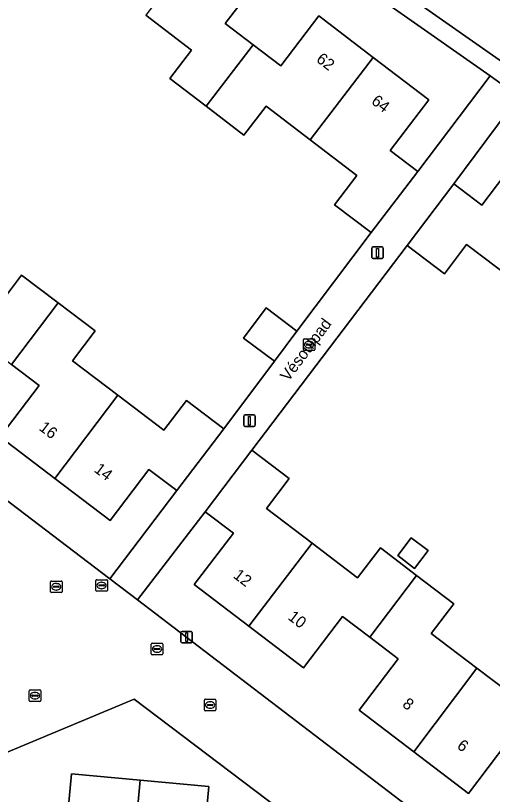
# Model space of a CAD drawing. Extents: x 158472 to 159562, y 388525 to 389606.
# Drawn here: x 158657.8 to 158699.2, y 389050.2 to 389117.7 of the extents above; entities that cross this region are included whole.
import ezdxf

# ---------------------------------------------------------------- set-up
doc = ezdxf.new("R2010")
doc.units = 0
for name, color, linetype in [('IMGEO_Brandkraan', 7, 'Continuous'), ('IMGEO_Erf', 7, 'Continuous'), ('IMGEO_Kolk', 7, 'Continuous'), ('IMGEO_Lichtmast', 7, 'Continuous'), ('IMGEO_Openbare_ruimte_label', 7, 'Continuous'), ('IMGEO_Pand', 7, 'Continuous'), ('IMGEO_Pand_nummerreeks', 7, 'Continuous'), ('IMGEO_Rijbaan_lokaal_open', 7, 'Continuous'), ('IMGEO_Rioolput', 7, 'Continuous')]:
    doc.layers.add(name, color=color, linetype=linetype)

msp = doc.modelspace()

# ---------------------------------------------------------------- linework, layer by layer
at = {"layer": 'IMGEO_Brandkraan'}
for p, q in [((158664.798, 389067.88), (158664.798, 389068.732)), ((158664.873, 389068.806), (158665.725, 389068.806)), ((158665.057, 389068.3), (158665.057, 389068.312)), ((158665.495, 389068.263), (158665.097, 389068.263)), ((158665.1, 389068.349), (158665.498, 389068.349)), ((158665.286, 389068.586), (158665.311, 389068.586)), ((158665.541, 389068.312), (158665.541, 389068.3)), ((158665.799, 389068.732), (158665.799, 389067.88)), ((158665.725, 389067.806), (158664.873, 389067.806)), ((158665.309, 389068.026), (158665.284, 389068.026))]:
    msp.add_line(p, q, dxfattribs=at)
for points in [[(158664.798, 389067.88), (158664.798, 389068.732)], [(158664.873, 389068.806), (158665.725, 389068.806)], [(158665.799, 389068.732), (158665.799, 389067.88)], [(158665.725, 389067.806), (158664.873, 389067.806)]]:
    msp.add_lwpolyline(points, dxfattribs=at)
for centre, radius, start, end in [((158664.875, 389068.73), 0.0765, 91.55205, 178.44795), ((158664.875, 389068.73), 0.0765, 91.55205, 178.44795), ((158665.097, 389068.309), 0.0403, 85.87752, 175.75265), ((158665.094, 389068.299), 0.0366, 178.93798, 274.71019), ((158665.498, 389068.306), 0.043, 264.86636, 352.45326), ((158665.502, 389068.311), 0.0386, 1.73085, 96.63898), ((158665.723, 389068.73), 0.0765, 1.55205, 88.44795), ((158665.723, 389068.73), 0.0765, 1.55205, 88.44795), ((158664.875, 389067.882), 0.0765, 181.55205, 268.44795), ((158664.875, 389067.882), 0.0765, 181.55205, 268.44795), ((158665.723, 389067.882), 0.0765, 271.55205, 358.44795), ((158665.723, 389067.882), 0.0765, 271.55205, 358.44795)]:
    msp.add_arc(centre, radius, start, end, dxfattribs=at)
for centre, major_axis, ratio, start_param, end_param in [((158665.285, 389068.306), (-0.387, 0.002), 0.722429, 4.712389, 7.853982), ((158665.31, 389068.306), (-0.39, 0.002), 0.717154, 1.570796, 4.712389)]:
    msp.add_ellipse(centre, major_axis=major_axis, ratio=ratio, start_param=start_param, end_param=end_param, dxfattribs=at)
at = {"layer": 'IMGEO_Erf'}
for points in [[(158679.33, 389121.365), (158676.023, 389117.031), (158678.428, 389115.197), (158680.826, 389113.367), (158684.126, 389117.692), (158688.842, 389114.094), (158693.667, 389110.414), (158690.325, 389106.033), (158692.708, 389104.215), (158698.976, 389112.491), (158667.837, 389134.355)], [(158656.42, 389092.671), (158658.359, 389095.225), (158661.535, 389092.814), (158664.749, 389090.375), (158662.781, 389087.782), (158666.701, 389084.807), (158670.701, 389081.771), (158672.66, 389084.353), (158675.89, 389081.901), (158680.277, 389087.743), (158677.592, 389089.759), (158679.554, 389092.371), (158682.238, 389090.356), (158688.657, 389098.904), (158685.492, 389101.318), (158687.434, 389103.864), (158683.39, 389106.949), (158679.556, 389109.874), (158677.637, 389107.357), (158674.355, 389109.86), (158671.208, 389112.261), (158673.09, 389114.728), (158669.124, 389117.753)], [(158701.475, 389110.704), (158695.827, 389103.12), (158698.265, 389101.272), (158701.633, 389105.715)], [(158618.796, 389104.84), (158666.009, 389068.886), (158671.82, 389076.538), (158669.4, 389078.375), (158666.038, 389073.946), (158661.229, 389077.596), (158656.491, 389081.192), (158659.878, 389085.654), (158657.482, 389087.472)], [(158700.955, 389094.828), (158696.945, 389097.868), (158695.017, 389095.325), (158691.779, 389097.78), (158678.338, 389080.036), (158681.568, 389077.578), (158679.589, 389074.979), (158683.544, 389071.969), (158687.495, 389068.962), (158689.476, 389071.565), (158692.61, 389069.18), (158695.844, 389066.719), (158693.885, 389064.144), (158697.825, 389061.145), (158701.84, 389058.089)], [(158705.458, 389048.349), (158703.8, 389052.306), (158700.533, 389054.791), (158697.101, 389050.282), (158692.361, 389053.889), (158687.621, 389057.497), (158691.015, 389061.956), (158688.544, 389063.837), (158686.188, 389065.629), (158682.802, 389061.179), (158678.073, 389064.778), (158673.33, 389068.387), (158676.725, 389072.848), (158674.283, 389074.706), (158668.409, 389067.056), (158697.03, 389045.201)], [(158695.038, 389031.866), (158693.979, 389034.415), (158691.297, 389040.872), (158689.958, 389044.098), (158688.082, 389043.319), (158668.118, 389058.458), (158641.722, 389047.425), (158602.187, 389030.899), (158601.851, 389031.612), (158596.34, 389029.317), (158593.802, 389028.26), (158586.677, 389025.294), (158575.064, 389020.458), (158573.349, 389019.024)]]:
    msp.add_lwpolyline(points, dxfattribs=at)
for points in [[(158692.44, 389069.784), (158690.971, 389070.901), (158692.145, 389072.444), (158693.614, 389071.326)], [(158659.147, 389046.676), (158662.176, 389046.394), (158662.695, 389051.981), (158668.642, 389051.428), (158674.589, 389050.875), (158674.068, 389045.284), (158677.089, 389045.003), (158676.626, 389040.025), (158676.481, 389038.46), (158672.517, 389038.829), (158672.8, 389041.871), (158667.798, 389042.337), (158662.904, 389042.792), (158662.606, 389039.583), (158658.522, 389039.963), (158658.684, 389041.698)]]:
    msp.add_lwpolyline(points, close=True, dxfattribs=at)
at = {"layer": 'IMGEO_Kolk'}
for p, q in [((158682.79, 389088.768), (158682.79, 389089.62)), ((158682.865, 389089.694), (158683.717, 389089.694)), ((158683.049, 389089.188), (158683.049, 389089.2)), ((158683.092, 389089.237), (158683.49, 389089.237)), ((158683.278, 389089.474), (158683.303, 389089.474)), ((158683.533, 389089.2), (158683.533, 389089.188)), ((158683.791, 389089.62), (158683.791, 389088.768)), ((158683.717, 389088.694), (158682.865, 389088.694)), ((158683.487, 389089.151), (158683.089, 389089.151)), ((158683.301, 389088.914), (158683.276, 389088.914)), ((158660.865, 389067.767), (158660.865, 389068.619)), ((158660.94, 389068.693), (158661.792, 389068.693)), ((158661.167, 389068.236), (158661.565, 389068.236)), ((158661.353, 389068.473), (158661.378, 389068.473)), ((158661.866, 389068.619), (158661.866, 389067.767)), ((158661.792, 389067.693), (158660.94, 389067.693)), ((158661.124, 389068.187), (158661.124, 389068.199)), ((158661.562, 389068.15), (158661.164, 389068.15)), ((158661.376, 389067.913), (158661.351, 389067.913)), ((158661.608, 389068.199), (158661.608, 389068.187)), ((158659.023, 389058.329), (158659.023, 389059.181)), ((158659.098, 389059.255), (158659.95, 389059.255)), ((158659.325, 389058.798), (158659.723, 389058.798)), ((158659.511, 389059.035), (158659.536, 389059.035)), ((158660.024, 389059.181), (158660.024, 389058.329)), ((158659.95, 389058.255), (158659.098, 389058.255)), ((158659.282, 389058.749), (158659.282, 389058.761)), ((158659.72, 389058.712), (158659.322, 389058.712)), ((158659.534, 389058.475), (158659.509, 389058.475)), ((158659.766, 389058.761), (158659.766, 389058.749)), ((158674.207, 389057.51), (158674.207, 389058.362)), ((158674.282, 389058.436), (158675.134, 389058.436)), ((158674.695, 389058.216), (158674.72, 389058.216)), ((158675.208, 389058.362), (158675.208, 389057.51)), ((158675.134, 389057.436), (158674.282, 389057.436)), ((158674.466, 389057.93), (158674.466, 389057.942)), ((158674.904, 389057.893), (158674.506, 389057.893)), ((158674.509, 389057.979), (158674.907, 389057.979)), ((158674.718, 389057.656), (158674.693, 389057.656)), ((158674.95, 389057.942), (158674.95, 389057.93))]:
    msp.add_line(p, q, dxfattribs=at)
for points in [[(158682.79, 389088.768), (158682.79, 389089.62)], [(158682.865, 389089.694), (158683.717, 389089.694)], [(158683.791, 389089.62), (158683.791, 389088.768)], [(158683.717, 389088.694), (158682.865, 389088.694)], [(158660.865, 389067.767), (158660.865, 389068.619)], [(158660.94, 389068.693), (158661.792, 389068.693)], [(158661.866, 389068.619), (158661.866, 389067.767)], [(158661.792, 389067.693), (158660.94, 389067.693)], [(158659.023, 389058.329), (158659.023, 389059.181)], [(158659.098, 389059.255), (158659.95, 389059.255)], [(158660.024, 389059.181), (158660.024, 389058.329)], [(158659.95, 389058.255), (158659.098, 389058.255)], [(158674.207, 389057.51), (158674.207, 389058.362)], [(158674.282, 389058.436), (158675.134, 389058.436)], [(158675.208, 389058.362), (158675.208, 389057.51)], [(158675.134, 389057.436), (158674.282, 389057.436)]]:
    msp.add_lwpolyline(points, dxfattribs=at)
for centre, radius, start, end in [((158682.867, 389089.618), 0.0765, 91.55205, 178.44795), ((158682.867, 389089.618), 0.0765, 91.55205, 178.44795), ((158683.089, 389089.197), 0.0403, 85.87752, 175.75265), ((158683.086, 389089.187), 0.0366, 178.93798, 274.71019), ((158683.49, 389089.194), 0.043, 264.86636, 352.45326), ((158683.494, 389089.199), 0.0386, 1.73085, 96.63898), ((158683.715, 389089.618), 0.0765, 1.55205, 88.44795), ((158683.715, 389089.618), 0.0765, 1.55205, 88.44795), ((158682.867, 389088.77), 0.0765, 181.55205, 268.44795), ((158682.867, 389088.77), 0.0765, 181.55205, 268.44795), ((158683.715, 389088.77), 0.0765, 271.55205, 358.44795), ((158683.715, 389088.77), 0.0765, 271.55205, 358.44795), ((158660.942, 389068.617), 0.0765, 91.55205, 178.44795), ((158660.942, 389068.617), 0.0765, 91.55205, 178.44795), ((158661.164, 389068.196), 0.0403, 85.87752, 175.75265), ((158661.569, 389068.198), 0.0386, 1.73085, 96.63898), ((158661.79, 389068.617), 0.0765, 1.55205, 88.44795), ((158661.79, 389068.617), 0.0765, 1.55205, 88.44795), ((158660.942, 389067.769), 0.0765, 181.55205, 268.44795), ((158660.942, 389067.769), 0.0765, 181.55205, 268.44795), ((158661.161, 389068.186), 0.0366, 178.93798, 274.71019), ((158661.565, 389068.193), 0.043, 264.86636, 352.45326), ((158661.79, 389067.769), 0.0765, 271.55205, 358.44795), ((158661.79, 389067.769), 0.0765, 271.55205, 358.44795), ((158659.1, 389059.179), 0.0765, 91.55205, 178.44795), ((158659.1, 389059.179), 0.0765, 91.55205, 178.44795), ((158659.322, 389058.758), 0.0403, 85.87752, 175.75265), ((158659.727, 389058.76), 0.0386, 1.73085, 96.63898), ((158659.948, 389059.179), 0.0765, 1.55205, 88.44795), ((158659.948, 389059.179), 0.0765, 1.55205, 88.44795), ((158659.1, 389058.331), 0.0765, 181.55205, 268.44795), ((158659.1, 389058.331), 0.0765, 181.55205, 268.44795), ((158659.319, 389058.748), 0.0366, 178.93798, 274.71019), ((158659.723, 389058.755), 0.043, 264.86636, 352.45326), ((158659.948, 389058.331), 0.0765, 271.55205, 358.44795), ((158659.948, 389058.331), 0.0765, 271.55205, 358.44795), ((158674.284, 389058.36), 0.0765, 91.55205, 178.44795), ((158674.284, 389058.36), 0.0765, 91.55205, 178.44795), ((158675.132, 389058.36), 0.0765, 1.55205, 88.44795), ((158675.132, 389058.36), 0.0765, 1.55205, 88.44795), ((158674.284, 389057.512), 0.0765, 181.55205, 268.44795), ((158674.284, 389057.512), 0.0765, 181.55205, 268.44795), ((158674.506, 389057.939), 0.0403, 85.87752, 175.75265), ((158674.503, 389057.929), 0.0366, 178.93798, 274.71019), ((158674.907, 389057.936), 0.043, 264.86636, 352.45326), ((158674.911, 389057.941), 0.0386, 1.73085, 96.63898), ((158675.132, 389057.512), 0.0765, 271.55205, 358.44795), ((158675.132, 389057.512), 0.0765, 271.55205, 358.44795)]:
    msp.add_arc(centre, radius, start, end, dxfattribs=at)
for centre, major_axis, ratio, start_param, end_param in [((158683.277, 389089.194), (-0.387, 0.002), 0.722429, 4.712389, 7.853982), ((158683.302, 389089.194), (-0.39, 0.002), 0.717154, 1.570796, 4.712389), ((158661.352, 389068.193), (-0.387, 0.002), 0.722429, 4.712389, 7.853982), ((158661.377, 389068.193), (-0.39, 0.002), 0.717154, 1.570796, 4.712389), ((158659.51, 389058.755), (-0.387, 0.002), 0.722429, 4.712389, 7.853982), ((158659.535, 389058.755), (-0.39, 0.002), 0.717154, 1.570796, 4.712389), ((158674.694, 389057.936), (-0.387, 0.002), 0.722429, 4.712389, 7.853982), ((158674.719, 389057.936), (-0.39, 0.002), 0.717154, 1.570796, 4.712389)]:
    msp.add_ellipse(centre, major_axis=major_axis, ratio=ratio, start_param=start_param, end_param=end_param, dxfattribs=at)
at = {"layer": 'IMGEO_Lichtmast'}
for p, q in [((158688.725, 389096.758), (158688.725, 389097.558)), ((158688.725, 389097.558), (158688.725, 389096.758)), ((158688.825, 389097.658), (158689.615, 389097.658)), ((158689.615, 389097.658), (158688.825, 389097.658)), ((158689.715, 389097.558), (158689.715, 389096.758)), ((158689.715, 389096.758), (158689.715, 389097.558)), ((158689.615, 389096.658), (158688.825, 389096.658)), ((158688.825, 389096.658), (158689.615, 389096.658)), ((158677.717, 389083.093), (158678.507, 389083.093)), ((158678.507, 389083.093), (158677.717, 389083.093)), ((158677.617, 389082.193), (158677.617, 389082.993)), ((158677.617, 389082.993), (158677.617, 389082.193)), ((158678.607, 389082.993), (158678.607, 389082.193)), ((158678.607, 389082.193), (158678.607, 389082.993)), ((158678.507, 389082.093), (158677.717, 389082.093)), ((158677.717, 389082.093), (158678.507, 389082.093)), ((158672.173, 389063.424), (158672.173, 389064.224)), ((158672.173, 389064.224), (158672.173, 389063.424)), ((158672.273, 389064.324), (158673.063, 389064.324)), ((158673.063, 389064.324), (158672.273, 389064.324)), ((158673.163, 389064.224), (158673.163, 389063.424)), ((158673.163, 389063.424), (158673.163, 389064.224)), ((158673.063, 389063.324), (158672.273, 389063.324)), ((158672.273, 389063.324), (158673.063, 389063.324))]:
    msp.add_line(p, q, dxfattribs=at)
for points in [[(158689.145, 389097.533), (158689.295, 389097.533), (158689.295, 389096.783), (158689.145, 389096.783), (158689.145, 389097.533)], [(158678.037, 389082.968), (158678.187, 389082.968), (158678.187, 389082.218), (158678.037, 389082.218), (158678.037, 389082.968)], [(158672.593, 389064.199), (158672.743, 389064.199), (158672.743, 389063.449), (158672.593, 389063.449), (158672.593, 389064.199)]]:
    msp.add_lwpolyline(points, dxfattribs=at)
for centre, start, end in [((158688.825, 389097.558), 90, 180), ((158688.825, 389097.558), 90, 180), ((158689.615, 389097.558), 0, 90), ((158689.615, 389097.558), 360, 90), ((158688.825, 389096.758), 180, 270), ((158688.825, 389096.758), 180, 270), ((158689.615, 389096.758), 270, 0), ((158689.615, 389096.758), 270, 0), ((158677.717, 389082.993), 90, 180), ((158677.717, 389082.993), 90, 180), ((158678.507, 389082.993), 0, 90), ((158678.507, 389082.993), 360, 90), ((158677.717, 389082.193), 180, 270), ((158677.717, 389082.193), 180, 270), ((158678.507, 389082.193), 270, 0), ((158678.507, 389082.193), 270, 0), ((158672.273, 389064.224), 90, 180), ((158672.273, 389064.224), 90, 180), ((158673.063, 389064.224), 0, 90), ((158673.063, 389064.224), 360, 90), ((158672.273, 389063.424), 180, 270), ((158672.273, 389063.424), 180, 270), ((158673.063, 389063.424), 270, 0), ((158673.063, 389063.424), 270, 0)]:
    msp.add_arc(centre, 0.1, start, end, dxfattribs=at)
at = {"layer": 'IMGEO_Pand'}
for points in [[(158674.355, 389109.86), (158678.428, 389115.197), (158676.023, 389117.031), (158679.33, 389121.365), (158674.62, 389124.957), (158669.124, 389117.753), (158673.09, 389114.728), (158671.208, 389112.261)], [(158683.39, 389106.949), (158688.842, 389114.094), (158684.126, 389117.692), (158680.826, 389113.367), (158678.428, 389115.197), (158674.355, 389109.86), (158677.637, 389107.357), (158679.556, 389109.874)], [(158683.39, 389106.949), (158687.434, 389103.864), (158685.492, 389101.318), (158688.657, 389098.904), (158692.708, 389104.215), (158690.325, 389106.033), (158693.667, 389110.414), (158688.842, 389114.094)], [(158700.955, 389094.828), (158706.446, 389102.066), (158701.633, 389105.715), (158698.265, 389101.272), (158695.827, 389103.12), (158691.779, 389097.78), (158695.017, 389095.325), (158696.945, 389097.868)], [(158657.482, 389087.472), (158661.535, 389092.814), (158658.359, 389095.225), (158656.42, 389092.671), (158652.463, 389095.674), (158646.967, 389088.432), (158651.682, 389084.853), (158655.063, 389089.308)], [(158657.482, 389087.472), (158659.878, 389085.654), (158656.491, 389081.192), (158661.229, 389077.596), (158666.701, 389084.807), (158662.781, 389087.782), (158664.749, 389090.375), (158661.535, 389092.814)], [(158682.238, 389090.356), (158679.554, 389092.371), (158677.592, 389089.759), (158680.277, 389087.743)], [(158661.229, 389077.596), (158666.038, 389073.946), (158669.4, 389078.375), (158671.82, 389076.538), (158675.89, 389081.901), (158672.66, 389084.353), (158670.701, 389081.771), (158666.701, 389084.807)], [(158683.544, 389071.969), (158679.589, 389074.979), (158681.568, 389077.578), (158678.338, 389080.036), (158674.283, 389074.706), (158676.725, 389072.848), (158673.33, 389068.387), (158678.073, 389064.778)], [(158690.971, 389070.901), (158692.44, 389069.784), (158693.614, 389071.326), (158692.145, 389072.444)], [(158683.544, 389071.969), (158678.073, 389064.778), (158682.802, 389061.179), (158686.188, 389065.629), (158688.544, 389063.837), (158692.61, 389069.18), (158689.476, 389071.565), (158687.495, 389068.962)], [(158697.825, 389061.145), (158693.885, 389064.144), (158695.844, 389066.719), (158692.61, 389069.18), (158688.544, 389063.837), (158691.015, 389061.956), (158687.621, 389057.497), (158692.361, 389053.889)], [(158697.825, 389061.145), (158692.361, 389053.889), (158697.101, 389050.282), (158700.533, 389054.791), (158703.8, 389052.306), (158709.319, 389056.434), (158703.785, 389060.645), (158701.84, 389058.089)], [(158667.798, 389042.337), (158668.642, 389051.428), (158662.695, 389051.981), (158662.176, 389046.394), (158659.147, 389046.676), (158658.684, 389041.698), (158658.522, 389039.963), (158662.606, 389039.583), (158662.904, 389042.792)], [(158667.798, 389042.337), (158672.8, 389041.871), (158672.517, 389038.829), (158676.481, 389038.46), (158676.626, 389040.025), (158677.089, 389045.003), (158674.068, 389045.284), (158674.589, 389050.875), (158668.642, 389051.428)]]:
    msp.add_lwpolyline(points, close=True, dxfattribs=at)
at = {"layer": 'IMGEO_Rijbaan_lokaal_open'}
for points in [[(158668.668, 389135.691), (158700.051, 389113.689), (158712.105, 389105.251), (158715.048, 389109.451), (158714.59, 389109.772), (158710.878, 389112.337), (158703.009, 389117.912), (158699.282, 389120.506), (158698.044, 389121.368), (158694.513, 389123.837), (158686.589, 389129.391), (158683.027, 389131.885), (158681.802, 389132.741), (158678.316, 389135.175), (158670.083, 389140.909), (158668.417, 389142.153), (158667.201, 389143.189), (158663.593, 389139.621)], [(158697.03, 389045.201), (158668.409, 389067.056), (158666.009, 389068.886), (158618.796, 389104.84), (158616.4, 389103.871), (158605.841, 389128.964), (158604.336, 389132.54), (158600.426, 389141.831)], [(158719.28, 389100.228), (158714.375, 389103.662), (158712.105, 389105.251), (158700.051, 389113.689), (158668.668, 389135.691)], [(158667.837, 389134.355), (158698.976, 389112.491), (158701.475, 389110.704), (158720.018, 389097.701)], [(158641.722, 389047.425), (158668.118, 389058.458), (158688.082, 389043.319)]]:
    msp.add_lwpolyline(points, dxfattribs=at)
msp.add_lwpolyline([(158691.779, 389097.78), (158695.827, 389103.12), (158701.475, 389110.704), (158698.976, 389112.491), (158692.708, 389104.215), (158688.657, 389098.904), (158682.238, 389090.356), (158680.277, 389087.743), (158675.89, 389081.901), (158671.82, 389076.538), (158666.009, 389068.886), (158668.409, 389067.056), (158674.283, 389074.706), (158678.338, 389080.036)], close=True, dxfattribs=at)
at = {"layer": 'IMGEO_Rioolput'}
for p, q in [((158669.609, 389062.377), (158669.609, 389063.229)), ((158669.684, 389063.303), (158670.536, 389063.303)), ((158669.911, 389062.846), (158670.309, 389062.846)), ((158670.097, 389063.083), (158670.122, 389063.083)), ((158670.61, 389063.229), (158670.61, 389062.377)), ((158670.536, 389062.303), (158669.684, 389062.303)), ((158669.868, 389062.797), (158669.868, 389062.809)), ((158670.306, 389062.76), (158669.908, 389062.76)), ((158670.12, 389062.523), (158670.095, 389062.523)), ((158670.352, 389062.809), (158670.352, 389062.797))]:
    msp.add_line(p, q, dxfattribs=at)
for points in [[(158669.609, 389062.377), (158669.609, 389063.229)], [(158669.684, 389063.303), (158670.536, 389063.303)], [(158670.61, 389063.229), (158670.61, 389062.377)], [(158670.536, 389062.303), (158669.684, 389062.303)]]:
    msp.add_lwpolyline(points, dxfattribs=at)
for centre, radius, start, end in [((158669.686, 389063.227), 0.0765, 91.55205, 178.44795), ((158669.686, 389063.227), 0.0765, 91.55205, 178.44795), ((158669.908, 389062.806), 0.0403, 85.87752, 175.75265), ((158670.313, 389062.808), 0.0386, 1.73085, 96.63898), ((158670.534, 389063.227), 0.0765, 1.55205, 88.44795), ((158670.534, 389063.227), 0.0765, 1.55205, 88.44795), ((158669.686, 389062.379), 0.0765, 181.55205, 268.44795), ((158669.686, 389062.379), 0.0765, 181.55205, 268.44795), ((158669.905, 389062.796), 0.0366, 178.93798, 274.71019), ((158670.309, 389062.803), 0.043, 264.86636, 352.45326), ((158670.534, 389062.379), 0.0765, 271.55205, 358.44795), ((158670.534, 389062.379), 0.0765, 271.55205, 358.44795)]:
    msp.add_arc(centre, radius, start, end, dxfattribs=at)
for centre, major_axis, ratio, start_param, end_param in [((158670.096, 389062.803), (-0.387, 0.002), 0.722429, 4.712389, 7.853982), ((158670.121, 389062.803), (-0.39, 0.002), 0.717154, 1.570796, 4.712389)]:
    msp.add_ellipse(centre, major_axis=major_axis, ratio=ratio, start_param=start_param, end_param=end_param, dxfattribs=at)

# ---------------------------------------------------------------- texts
at = {"layer": 'IMGEO_Openbare_ruimte_label'}
msp.add_text('Vésoulpad', height=1, rotation=52.96961, dxfattribs=at).set_placement((158681.486, 389085.937))
at = {"layer": 'IMGEO_Pand_nummerreeks'}
for s, rotation, p in [('62', 322.64519, (158683.834, 389113.788)), ('64', 322.68067, (158688.609, 389110.146)), ('16', 322.80216, (158659.798, 389081.846)), ('14', 322.80216, (158664.572, 389078.223)), ('12', 322.7296, (158676.641, 389069.035)), ('10', 322.7296, (158681.381, 389065.427)), ('8', 322.72611, (158691.301, 389057.863)), ('6', 322.72611, (158696.038, 389054.257))]:
    msp.add_text(s, height=1, rotation=rotation, dxfattribs=at).set_placement(p)

doc.saveas('drawing.dxf')
